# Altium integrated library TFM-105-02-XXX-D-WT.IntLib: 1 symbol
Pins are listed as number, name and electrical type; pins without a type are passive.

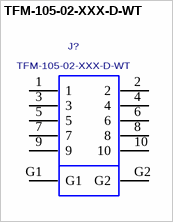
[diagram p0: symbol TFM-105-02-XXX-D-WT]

## TFM-105-02-XXX-D-WT
designator J?
0.050" TERMINAL STRIP, SURFACE MOUNT ASSEMBLY.; MANUFACTURER: SAMTEC
footprint TFM-105-02-XXX-D-WT
pins: 1, 2, 3, 4, 5, 6, 7, 8, 9, 10, G1, G2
